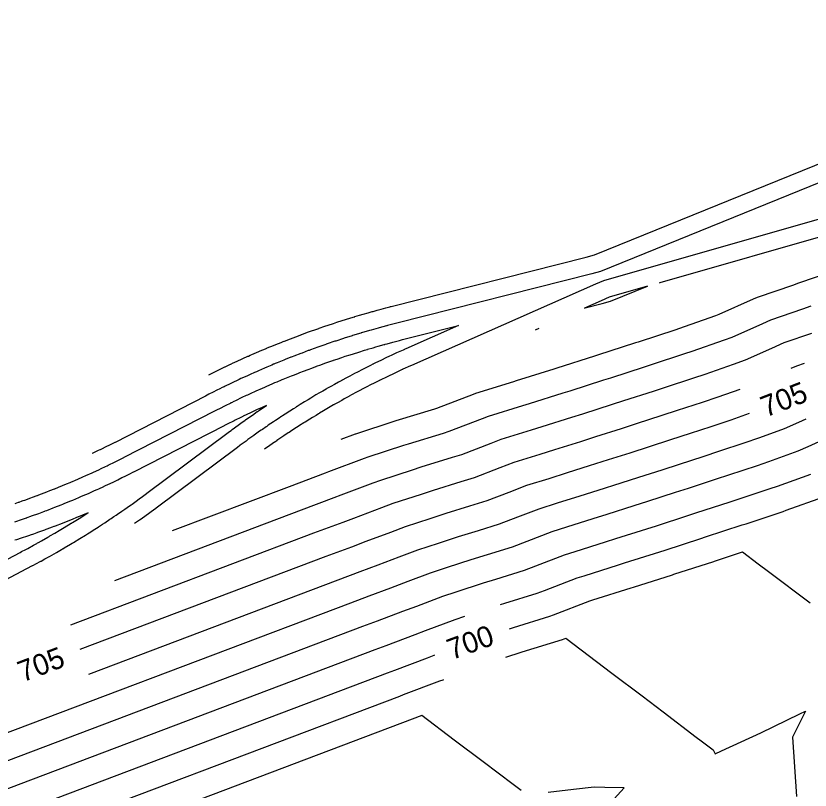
# Model space of a CAD drawing. Extents: x 1487507 to 1489130, y 497211 to 499439.
# Drawn here: x 1488049 to 1488139.6, y 498566.4 to 498654.7 of the extents above; entities that cross this region are included whole.
import ezdxf

# ---------------------------------------------------------------- set-up
doc = ezdxf.new("R2010")
doc.units = 0
for name, color, linetype in [('Prop CMT Ditch DDE', 7, 'Continuous'), ('Prop Drainage Ditch Flow Line', 7, 'Continuous'), ('Prop Drainage Structure Pipe Outlet Channel Detail CELL', 7, 'Continuous')]:
    doc.layers.add(name, color=color, linetype=linetype)

msp = doc.modelspace()

# ---------------------------------------------------------------- linework, layer by layer
at = {"layer": 'Prop CMT Ditch DDE'}
for points in [[(1488187.499, 498654.722), (1488115.641, 498625.576), (1488114.672, 498625.319), (1488092.441, 498619.692), (1488092.429, 498619.689), (1488092.293, 498619.654), (1488091.351, 498619.407), (1488091.297, 498619.393), (1488091.251, 498619.381), (1488090.401, 498619.149), (1488090.303, 498619.121), (1488090.281, 498619.115), (1488089.513, 498618.897), (1488089.316, 498618.841), (1488089.311, 498618.84), (1488088.394, 498618.57), (1488088.369, 498618.562), (1488088.321, 498618.548), (1488087.383, 498618.261), (1488087.333, 498618.246), (1488086.419, 498617.956), (1488086.346, 498617.933), (1488085.457, 498617.642), (1488085.365, 498617.611), (1488084.497, 498617.317), (1488084.385, 498617.279), (1488084.333, 498617.261), (1488083.532, 498616.98), (1488083.407, 498616.936), (1488082.584, 498616.639), (1488082.431, 498616.583), (1488082.348, 498616.552), (1488082.332, 498616.546), (1488081.614, 498616.279), (1488081.459, 498616.22), (1488080.681, 498615.922), (1488080.49, 498615.847), (1488080.372, 498615.801), (1488080.342, 498615.789), (1488079.703, 498615.536), (1488079.523, 498615.464), (1488078.791, 498615.166), (1488078.56, 498615.071), (1488078.413, 498615.01), (1488078.365, 498614.99), (1488078.171, 498614.908), (1488077.6, 498614.668), (1488077.34, 498614.555), (1488076.643, 498614.255), (1488076.573, 498614.224), (1488076.401, 498614.149), (1488076.186, 498614.053), (1488075.69, 498613.832), (1488075.377, 498613.689), (1488074.74, 498613.399), (1488074.639, 498613.353), (1488074.452, 498613.266), (1488074.212, 498613.152), (1488073.794, 498612.957), (1488073.422, 498612.777), (1488072.851, 498612.504), (1488072.713, 498612.436), (1488072.519, 498612.341), (1488072.255, 498612.21), (1488071.913, 498612.041), (1488071.475, 498611.819), (1488070.978, 498611.569), (1488070.793, 498611.473), (1488070.602, 498611.375), (1488060.279, 498606.087), (1488060.247, 498606.071), (1488059.485, 498605.69), (1488059.398, 498605.647), (1488058.59, 498605.254), (1488058.545, 498605.231), (1488058.368, 498605.146), (1488058.36, 498605.143), (1488057.691, 498604.826), (1488057.658, 498604.811)], [(1488179.979, 498642.811), (1488116.004, 498624.524), (1488115.082, 498624.13), (1488094.104, 498614.867), (1488094.092, 498614.861), (1488093.971, 498614.807), (1488093.131, 498614.427), (1488093.08, 498614.405), (1488093.037, 498614.385), (1488092.282, 498614.034), (1488092.195, 498613.993), (1488091.324, 498613.579), (1488091.314, 498613.573), (1488090.538, 498613.195), (1488090.48, 498613.166), (1488090.438, 498613.145), (1488089.682, 498612.767), (1488089.567, 498612.708), (1488088.867, 498612.349), (1488088.701, 498612.263), (1488088.7, 498612.263), (1488088.055, 498611.923), (1488087.841, 498611.81), (1488087.248, 498611.49), (1488086.986, 498611.348), (1488086.941, 498611.324), (1488086.429, 498611.041), (1488086.136, 498610.878), (1488085.646, 498610.601), (1488085.292, 498610.401), (1488085.244, 498610.373), (1488085.206, 498610.351), (1488084.813, 498610.123), (1488084.454, 498609.914), (1488084.063, 498609.683), (1488083.621, 498609.42), (1488083.566, 498609.388), (1488083.494, 498609.344), (1488083.209, 498609.171), (1488082.794, 498608.919), (1488082.502, 498608.738), (1488081.972, 498608.409), (1488081.857, 498608.336), (1488081.806, 498608.304), (1488081.329, 498608), (1488081.157, 498607.891), (1488080.965, 498607.767), (1488080.348, 498607.366), (1488080.309, 498607.34), (1488080.143, 498607.231), (1488080.04, 498607.163), (1488079.544, 498606.833), (1488079.437, 498606.76), (1488078.747, 498606.292), (1488078.725, 498606.277), (1488078.506, 498606.126), (1488078.465, 498606.098), (1488077.956, 498605.744), (1488077.925, 498605.722), (1488077.322, 498605.296)], [(1488142.268, 498625.6), (1488138.142, 498624.192), (1488137.683, 498624.033), (1488133.535, 498622.611), (1488133.093, 498622.413), (1488129.148, 498620.661), (1488128.762, 498620.523), (1488124.575, 498619.041), (1488124.26, 498618.937), (1488119.947, 498617.532), (1488119.652, 498617.435), (1488115.318, 498616.037), (1488114.988, 498615.93), (1488110.688, 498614.558), (1488110.34, 498614.448), (1488106.049, 498613.107), (1488105.738, 498613.009), (1488101.414, 498611.664), (1488101.127, 498611.553), (1488096.934, 498609.951), (1488096.722, 498609.885), (1488092.3, 498608.531), (1488092.185, 498608.493), (1488087.711, 498607.042), (1488087.685, 498607.032), (1488086.052, 498606.418)], [(1488139.661, 498621.604), (1488138.704, 498621.272), (1488135.044, 498620.018), (1488134.131, 498619.61), (1488130.649, 498618.063), (1488129.774, 498617.75), (1488126.067, 498616.438), (1488125.26, 498616.172), (1488121.43, 498614.924), (1488120.652, 498614.669), (1488116.792, 498613.424), (1488115.994, 498613.165), (1488112.153, 498611.94), (1488111.349, 498611.685), (1488107.506, 498610.484), (1488106.744, 498610.244), (1488102.862, 498609.036), (1488102.147, 498608.76), (1488098.373, 498607.318), (1488097.724, 498607.116), (1488093.73, 498605.893), (1488093.185, 498605.714), (1488089.132, 498604.399), (1488088.686, 498604.23), (1488084.644, 498602.711), (1488084.268, 498602.57), (1488080.129, 498601.027), (1488066.786, 498595.982)], [(1488048.888, 498599.128), (1488049.261, 498599.256), (1488049.35, 498599.287), (1488049.702, 498599.41), (1488049.793, 498599.442), (1488049.989, 498599.513), (1488050.696, 498599.766), (1488050.881, 498599.834), (1488051.384, 498600.019), (1488051.451, 498600.044), (1488051.596, 498600.098), (1488051.903, 498600.216), (1488052.494, 498600.441), (1488052.859, 498600.585), (1488053.389, 498600.792), (1488053.406, 498600.799), (1488053.816, 498600.966), (1488054.281, 498601.153), (1488054.747, 498601.348), (1488055.17, 498601.523), (1488055.305, 498601.581), (1488055.413, 498601.626), (1488055.783, 498601.786), (1488056.056, 498601.903), (1488056.594, 498602.14), (1488056.939, 498602.292), (1488057.236, 498602.426), (1488057.404, 498602.501), (1488057.677, 498602.625), (1488057.819, 498602.69), (1488058.42, 498602.969), (1488058.695, 498603.097), (1488059.186, 498603.331), (1488059.38, 498603.422), (1488059.518, 498603.489), (1488059.568, 498603.513), (1488060.226, 498603.835), (1488060.438, 498603.938), (1488061.122, 498604.282), (1488061.304, 498604.373), (1488061.337, 498604.39), (1488071.66, 498609.678), (1488071.98, 498609.843), (1488072.029, 498609.868), (1488072.156, 498609.931), (1488072.947, 498610.329), (1488073.435, 498610.57), (1488073.542, 498610.623), (1488073.602, 498610.652), (1488073.868, 498610.782), (1488074.053, 498610.869), (1488074.793, 498611.224), (1488075.286, 498611.455), (1488075.44, 498611.527), (1488075.509, 498611.559), (1488075.722, 498611.657), (1488076.399, 498611.965), (1488076.654, 498612.08), (1488076.856, 498612.169), (1488077.353, 498612.39), (1488077.517, 498612.462), (1488077.59, 498612.494), (1488078.218, 498612.764), (1488078.529, 498612.897), (1488078.792, 498613.007), (1488079.28, 498613.212), (1488079.35, 498613.241), (1488079.472, 498613.291), (1488080.049, 498613.526), (1488080.417, 498613.675), (1488080.748, 498613.806), (1488081.22, 498613.993), (1488081.303, 498614.025), (1488081.366, 498614.049), (1488081.789, 498614.211), (1488082.317, 498614.414), (1488082.723, 498614.564), (1488083.173, 498614.732), (1488083.223, 498614.751), (1488083.271, 498614.768), (1488083.756, 498614.942), (1488084.228, 498615.113), (1488084.652, 498615.261), (1488085.138, 498615.43), (1488085.165, 498615.439), (1488085.188, 498615.447), (1488085.607, 498615.589), (1488086.15, 498615.772), (1488086.542, 498615.9), (1488087.113, 498616.086), (1488087.115, 498616.086), (1488087.479, 498616.202), (1488088.082, 498616.391), (1488088.723, 498616.586), (1488089.051, 498616.686), (1488089.082, 498616.695), (1488089.098, 498616.7), (1488089.739, 498616.887), (1488090.022, 498616.97), (1488090.303, 498617.05), (1488090.995, 498617.245), (1488091.066, 498617.265), (1488091.091, 498617.272), (1488091.317, 498617.333), (1488091.97, 498617.51), (1488092.74, 498617.71), (1488092.947, 498617.764), (1488092.977, 498617.772), (1488093.093, 498617.801), (1488099.475, 498619.417), (1488093.453, 498616.757), (1488093.343, 498616.709), (1488093.317, 498616.697), (1488093.132, 498616.614), (1488092.407, 498616.288), (1488091.792, 498616.005), (1488091.592, 498615.911), (1488091.525, 498615.88), (1488091.502, 498615.87), (1488091.265, 498615.756), (1488090.603, 498615.443), (1488090.011, 498615.156), (1488089.751, 498615.029), (1488089.722, 498615.014), (1488089.708, 498615.007), (1488089.419, 498614.862), (1488088.819, 498614.563), (1488088.504, 498614.401), (1488087.935, 498614.111), (1488087.933, 498614.11), (1488087.593, 498613.931), (1488087.056, 498613.649), (1488086.691, 498613.453), (1488086.182, 498613.18), (1488086.157, 498613.166), (1488086.137, 498613.155), (1488085.767, 498612.951), (1488085.315, 498612.702), (1488084.901, 498612.468), (1488084.452, 498612.216), (1488084.409, 498612.191), (1488084.364, 498612.165), (1488083.971, 498611.937), (1488083.596, 498611.721), (1488083.203, 498611.49), (1488082.745, 498611.218), (1488082.673, 498611.175), (1488082.615, 498611.141), (1488082.308, 498610.955), (1488081.9, 498610.708), (1488081.393, 498610.394), (1488081.061, 498610.189), (1488080.956, 498610.123), (1488080.891, 498610.082), (1488080.646, 498609.927), (1488080.227, 498609.662), (1488079.676, 498609.305), (1488079.4, 498609.127), (1488079.258, 498609.034), (1488079.192, 498608.99), (1488079.002, 498608.865), (1488078.579, 498608.585), (1488078.347, 498608.428), (1488077.765, 498608.034), (1488077.581, 498607.909), (1488077.518, 498607.866), (1488077.09, 498607.568), (1488076.956, 498607.476), (1488076.775, 498607.349), (1488076.154, 498606.911), (1488076.097, 498606.87), (1488075.871, 498606.709), (1488075.448, 498606.402), (1488075.358, 498606.337), (1488075.227, 498606.241), (1488074.569, 498605.757), (1488074.525, 498605.724), (1488074.252, 498605.52), (1488064.958, 498598.581), (1488064.926, 498598.557), (1488064.393, 498598.166), (1488064.089, 498597.943), (1488063.404, 498597.45), (1488063.246, 498597.336), (1488063.087, 498597.224), (1488063.062, 498597.206), (1488062.514, 498596.821)], [(1488139.724, 498618.512), (1488136.554, 498617.425), (1488135.17, 498616.807), (1488132.149, 498615.465), (1488130.786, 498614.977), (1488127.559, 498613.835), (1488126.26, 498613.406), (1488122.913, 498612.316), (1488121.653, 498611.903), (1488118.266, 498610.811), (1488117, 498610.401), (1488113.618, 498609.322), (1488112.358, 498608.922), (1488108.962, 498607.861), (1488107.751, 498607.478), (1488104.309, 498606.408), (1488103.167, 498605.967), (1488099.812, 498604.685), (1488098.726, 498604.347), (1488095.159, 498603.256), (1488094.185, 498602.935), (1488090.552, 498601.757), (1488089.687, 498601.428), (1488086.055, 498600.064), (1488085.26, 498599.765), (1488081.532, 498598.375), (1488060.213, 498590.314)], [(1488137.42, 498614.545), (1488138.063, 498614.832), (1488138.933, 498615.13)], [(1488131.559, 498612.12), (1488129.051, 498611.232), (1488127.26, 498610.641), (1488124.396, 498609.707), (1488122.653, 498609.137), (1488119.74, 498608.198), (1488118.006, 498607.636), (1488115.084, 498606.704), (1488113.366, 498606.159), (1488110.418, 498605.238), (1488108.757, 498604.713), (1488105.757, 498603.78), (1488104.187, 498603.175), (1488101.25, 498602.052), (1488099.728, 498601.579), (1488096.589, 498600.618), (1488095.185, 498600.156), (1488091.973, 498599.114), (1488090.688, 498598.627), (1488087.467, 498597.416), (1488086.251, 498596.959), (1488082.936, 498595.724), (1488055.203, 498585.237)], [(1488044.664, 498588.773), (1488050.221, 498591.691), (1488050.875, 498592.036), (1488050.901, 498592.049), (1488051.748, 498592.505), (1488051.808, 498592.537), (1488051.84, 498592.555), (1488052.268, 498592.789), (1488052.667, 498593.011), (1488052.709, 498593.034), (1488052.799, 498593.085), (1488053.604, 498593.54), (1488054.185, 498593.874), (1488054.285, 498593.932), (1488054.316, 498593.95), (1488054.494, 498594.054), (1488055.218, 498594.482), (1488055.377, 498594.576), (1488055.546, 498594.679), (1488056.255, 498595.107), (1488056.272, 498595.118), (1488056.923, 498595.521), (1488057.127, 498595.647), (1488057.345, 498595.786), (1488057.992, 498596.195), (1488058.162, 498596.303), (1488058.228, 498596.346), (1488058.408, 498596.463), (1488058.851, 498596.75), (1488059.118, 498596.928), (1488059.703, 498597.314), (1488059.856, 498597.417), (1488060.152, 498597.616), (1488060.407, 498597.789), (1488060.55, 498597.887), (1488061.069, 498598.245), (1488061.389, 498598.467), (1488061.653, 498598.653), (1488062.043, 498598.927), (1488062.118, 498598.981), (1488062.223, 498599.055), (1488062.686, 498599.388), (1488063.049, 498599.651), (1488063.433, 498599.934), (1488063.869, 498600.255), (1488063.9, 498600.278), (1488073.194, 498607.217), (1488073.244, 498607.254), (1488073.518, 498607.458), (1488073.631, 498607.542), (1488074.324, 498608.049), (1488074.797, 498608.39), (1488074.848, 498608.427), (1488074.876, 498608.447), (1488075.137, 498608.633), (1488075.205, 498608.681), (1488075.956, 498609.209), (1488076.509, 498609.59), (1488076.531, 498609.605), (1488076.775, 498609.772), (1488076.782, 498609.777), (1488076.805, 498609.792), (1488077.568, 498610.305), (1488076.73, 498609.927), (1488076.704, 498609.915), (1488076.696, 498609.911), (1488076.427, 498609.787), (1488075.83, 498609.509), (1488075.793, 498609.492), (1488075.737, 498609.465), (1488074.885, 498609.059), (1488074.856, 498609.045), (1488074.565, 498608.904), (1488074.05, 498608.652), (1488073.981, 498608.618), (1488073.868, 498608.561), (1488073.081, 498608.166), (1488072.776, 498608.011), (1488072.717, 498607.981), (1488062.395, 498602.693), (1488062.361, 498602.675), (1488061.935, 498602.46), (1488061.478, 498602.23), (1488061.076, 498602.032), (1488060.591, 498601.795), (1488060.483, 498601.742), (1488060.399, 498601.701), (1488060.105, 498601.561), (1488059.701, 498601.368), (1488059.154, 498601.113), (1488058.807, 498600.951), (1488058.54, 498600.829), (1488058.385, 498600.758), (1488058.215, 498600.681), (1488057.91, 498600.543), (1488057.303, 498600.275), (1488057.009, 498600.145), (1488056.806, 498600.057), (1488056.354, 498599.862), (1488056.177, 498599.787), (1488056.106, 498599.756), (1488055.438, 498599.477), (1488055.199, 498599.376), (1488054.514, 498599.098), (1488054.306, 498599.013), (1488054.289, 498599.006), (1488054.09, 498598.927), (1488053.376, 498598.646), (1488053.203, 498598.579), (1488052.461, 498598.295), (1488052.279, 498598.227), (1488052.244, 498598.214), (1488052.137, 498598.174), (1488051.543, 498597.954), (1488050.719, 498597.657), (1488050.622, 498597.622), (1488050.209, 498597.476), (1488050.169, 498597.462), (1488050.128, 498597.448), (1488049.698, 498597.299), (1488048.812, 498597)], [(1488057.309, 498579.669), (1488085.743, 498590.42), (1488088.235, 498591.349), (1488090.291, 498592.121), (1488092.69, 498593.023), (1488094.814, 498593.829), (1488097.184, 498594.598), (1488099.448, 498595.342), (1488101.732, 498596.041), (1488104.127, 498596.786), (1488106.228, 498597.589), (1488108.652, 498598.524), (1488110.77, 498599.183), (1488113.331, 498599.992), (1488115.384, 498600.633), (1488118.014, 498601.467), (1488120.019, 498602.107), (1488122.689, 498602.971), (1488124.654, 498603.605), (1488127.362, 498604.491), (1488129.261, 498605.11), (1488132.035, 498606.026), (1488133.82, 498606.658), (1488136.651, 498607.671), (1488138.285, 498608.397), (1488139.112, 498608.766)], [(1488142.592, 498607.053), (1488139.324, 498605.593), (1488138.152, 498605.073), (1488134.832, 498603.885), (1488133.526, 498603.423), (1488130.261, 498602.344), (1488128.845, 498601.883), (1488125.655, 498600.839), (1488124.163, 498600.358), (1488121.025, 498599.342), (1488119.479, 498598.849), (1488116.393, 498597.87), (1488114.788, 498597.369), (1488111.776, 498596.417), (1488110.099, 498595.896), (1488107.248, 498594.796), (1488105.566, 498594.153), (1488102.734, 498593.273), (1488100.878, 498592.705), (1488098.184, 498591.819), (1488096.235, 498591.186), (1488093.691, 498590.221), (1488091.702, 498589.474), (1488089.227, 498588.544), (1488087.147, 498587.769), (1488040.009, 498569.944)], [(1488041.413, 498567.293), (1488088.551, 498585.117), (1488090.219, 498585.739), (1488093.114, 498586.826), (1488094.692, 498587.42), (1488097.656, 498588.544), (1488099.184, 498589.039), (1488102.308, 498590.067), (1488103.737, 498590.504), (1488107.005, 498591.52), (1488108.268, 498592.003), (1488111.547, 498593.268), (1488112.783, 498593.652), (1488116.244, 498594.746), (1488117.401, 498595.107), (1488120.945, 498596.231), (1488122.031, 498596.578), (1488125.637, 498597.745), (1488126.656, 498598.073), (1488130.328, 498599.275), (1488131.262, 498599.579), (1488135.018, 498600.82), (1488135.843, 498601.112), (1488139.652, 498602.475)], [(1488104.254, 498587.587), (1488104.739, 498587.735), (1488108.443, 498588.887), (1488109.288, 498589.21), (1488112.994, 498590.64), (1488113.789, 498590.887), (1488117.701, 498592.122), (1488118.41, 498592.344), (1488122.41, 498593.613), (1488123.037, 498593.813), (1488127.111, 498595.132), (1488127.656, 498595.307), (1488131.811, 498596.667), (1488132.262, 498596.814), (1488136.51, 498598.216), (1488136.855, 498598.338), (1488141.153, 498599.876)], [(1488043.886, 498590.615), (1488049.443, 498593.533), (1488049.622, 498593.628), (1488050.109, 498593.886), (1488050.326, 498594.003), (1488050.998, 498594.366), (1488051.354, 498594.562), (1488051.448, 498594.614), (1488051.536, 498594.662), (1488051.881, 498594.855), (1488052.614, 498595.271), (1488052.758, 498595.352), (1488052.862, 498595.412), (1488053.424, 498595.737), (1488053.603, 498595.842), (1488053.629, 498595.857), (1488053.738, 498595.921), (1488054.495, 498596.371), (1488055.295, 498596.857), (1488055.355, 498596.893), (1488055.371, 498596.903), (1488055.425, 498596.937), (1488056.208, 498597.424), (1488057.051, 498597.959), (1488057.057, 498597.963), (1488057.206, 498598.059), (1488057.042, 498597.989), (1488057.037, 498597.986), (1488056.117, 498597.6), (1488056.085, 498597.587), (1488055.207, 498597.228), (1488055.19, 498597.221), (1488054.343, 498596.884), (1488054.259, 498596.851), (1488053.436, 498596.534), (1488053.325, 498596.492), (1488053.298, 498596.481), (1488053.105, 498596.408), (1488052.495, 498596.181), (1488052.389, 498596.141), (1488052.242, 498596.088), (1488051.45, 498595.801), (1488051.365, 498595.771), (1488050.988, 498595.638), (1488050.608, 498595.505), (1488050.508, 498595.471), (1488050.303, 498595.401), (1488049.564, 498595.15), (1488049.04, 498594.977), (1488048.859, 498594.917)], [(1488017.17, 498554.642), (1488019.272, 498555.683), (1488023.971, 498557.494), (1488028.68, 498559.284), (1488033.391, 498561.072), (1488038.103, 498562.858), (1488042.817, 498564.641), (1488089.955, 498582.465), (1488091.211, 498582.934), (1488094.526, 498584.179), (1488095.693, 498584.618), (1488099.077, 498585.901), (1488100.17, 498586.256)], [(1488104.852, 498581.58), (1488106.597, 498582.153), (1488106.743, 498582.198), (1488111.32, 498583.621), (1488111.328, 498583.624), (1488111.711, 498583.772), (1488116.949, 498579.784), (1488120.399, 498577.196), (1488122.799, 498575.345), (1488126.562, 498572.484), (1488127.148, 498572.036), (1488128.499, 498571.01), (1488128.539, 498570.938), (1488128.742, 498570.573), (1488129.475, 498570.916), (1488133.964, 498572.969), (1488138.399, 498575.122), (1488139.029, 498575.427), (1488138.651, 498574.677), (1488137.545, 498572.487), (1488138.032, 498565.7)], [(1488022.193, 498550.423), (1488026.778, 498552.191), (1488031.488, 498553.981), (1488036.199, 498555.769), (1488040.911, 498557.554), (1488045.624, 498559.338), (1488092.762, 498577.162), (1488093.195, 498577.323), (1488097.349, 498578.884), (1488097.695, 498579.014), (1488097.794, 498579.052)], [(1488106.6, 498566.401), (1488105.708, 498567.069), (1488102.274, 498569.65), (1488098.977, 498572.126), (1488095.285, 498574.931), (1488094.187, 498574.518), (1488094.166, 498574.51), (1488047.028, 498556.686)], [(1488117.224, 498565.453), (1488118.372, 498566.675), (1488116.136, 498566.725), (1488114.944, 498566.752), (1488112.566, 498566.493), (1488109.68, 498566.177)]]:
    msp.add_lwpolyline(points, dxfattribs=at)
at = {"layer": 'Prop Drainage Ditch Flow Line'}
for points in [[(1488070.985, 498613.806), (1488071.496, 498614.06), (1488071.505, 498614.064), (1488071.835, 498614.226), (1488071.878, 498614.247), (1488072.794, 498614.689), (1488072.856, 498614.718), (1488073.465, 498615.005), (1488073.5, 498615.022), (1488073.758, 498615.142), (1488073.89, 498615.202), (1488074.725, 498615.584), (1488074.854, 498615.641), (1488075.449, 498615.908), (1488075.5, 498615.93), (1488075.696, 498616.017), (1488075.903, 498616.106), (1488076.67, 498616.439), (1488076.853, 498616.516), (1488077.449, 498616.768), (1488077.598, 498616.831), (1488077.648, 498616.851), (1488078.369, 498617.147), (1488078.629, 498617.253), (1488079.227, 498617.493), (1488079.463, 498617.586), (1488079.57, 498617.628), (1488079.614, 498617.645), (1488080.301, 498617.912), (1488080.601, 498618.027), (1488081.205, 498618.254), (1488081.49, 498618.361), (1488081.558, 498618.386), (1488081.592, 498618.398), (1488082.247, 498618.637), (1488082.585, 498618.759), (1488083.192, 498618.974), (1488083.529, 498619.092), (1488083.562, 498619.104), (1488083.581, 498619.11), (1488084.206, 498619.324), (1488084.58, 498619.451), (1488085.19, 498619.653), (1488085.581, 498619.781), (1488085.581, 498619.781), (1488086.18, 498619.972), (1488086.585, 498620.101), (1488087.17, 498620.281), (1488087.592, 498620.41), (1488087.62, 498620.419), (1488087.64, 498620.425), (1488088.184, 498620.587), (1488088.6, 498620.709), (1488089.158, 498620.869), (1488089.611, 498620.998), (1488089.665, 498621.013), (1488089.711, 498621.026), (1488090.201, 498621.161), (1488090.624, 498621.276), (1488091.165, 498621.42), (1488091.638, 498621.544), (1488091.717, 498621.565), (1488091.79, 498621.583), (1488114.02, 498627.21), (1488114.989, 498627.467), (1488173.682, 498651.273)], [(1488143.165, 498630.211), (1488122.433, 498624.285), (1488122.337, 498624.257)], [(1488108.264, 498618.94), (1488108.646, 498619.109)], [(1488132.625, 498609.366), (1488130.543, 498608.629), (1488128.261, 498607.875), (1488125.879, 498607.099), (1488123.654, 498606.371), (1488121.215, 498605.584), (1488119.012, 498604.872), (1488116.549, 498604.085), (1488114.375, 498603.396), (1488111.875, 498602.615), (1488109.764, 498601.948), (1488107.204, 498601.152), (1488105.208, 498600.382), (1488102.689, 498599.419), (1488100.73, 498598.81), (1488098.019, 498597.98), (1488096.185, 498597.377), (1488093.394, 498596.471), (1488091.689, 498595.825), (1488088.879, 498594.769), (1488087.243, 498594.154), (1488084.34, 498593.072), (1488056.256, 498582.453)], [(1488105.266, 498584.822), (1488105.741, 498584.967), (1488109.882, 498586.254), (1488110.308, 498586.417), (1488114.442, 498588.012), (1488114.795, 498588.122), (1488119.157, 498589.499), (1488119.419, 498589.581), (1488123.875, 498590.995), (1488124.043, 498591.048), (1488128.585, 498592.519), (1488128.657, 498592.541), (1488131.861, 498593.59), (1488133.659, 498592.236), (1488134.82, 498591.375), (1488139.591, 498587.801)], [(1488021.028, 498553.167), (1488025.374, 498554.842), (1488030.084, 498556.632), (1488034.795, 498558.42), (1488039.507, 498560.206), (1488044.22, 498561.989), (1488091.358, 498579.814), (1488092.203, 498580.128), (1488095.938, 498581.532), (1488096.694, 498581.816), (1488096.772, 498581.845)]]:
    msp.add_lwpolyline(points, dxfattribs=at)
msp.add_lwpolyline([(1488113.899, 498621.423), (1488115.845, 498621.916), (1488116.814, 498622.173), (1488121.038, 498623.886), (1488116.655, 498622.633), (1488115.734, 498622.239), (1488113.85, 498621.407)], close=True, dxfattribs=at)

# ---------------------------------------------------------------- texts
at = {"layer": 'Prop Drainage Structure Pipe Outlet Channel Detail CELL'}
for s, rotation, p in [('705', 21.15499, (1488134.504, 498608.913)), ('700', 20.09293, (1488098.697, 498581.245)), ('705', 20.71305, (1488049.749, 498578.709))]:
    msp.add_text(s, height=2.4, rotation=rotation, dxfattribs=at).set_placement(p)

doc.saveas('drawing.dxf')
